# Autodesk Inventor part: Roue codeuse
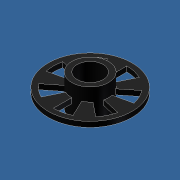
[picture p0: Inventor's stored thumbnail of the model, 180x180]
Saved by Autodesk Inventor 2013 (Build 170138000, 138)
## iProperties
Created: 2011-10
Part Number: Roue codeuse
Material: ABS (plastique)
Document SubType Name: Modeling
Designer: Laur
Mass: 0.0367757 g
Surface Area: 1.54299 cm^2
Volume: 0.034694 cm^3
Density: 1.06 g/cm^3
Author: Laur
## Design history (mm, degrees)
sketch "Esquisse3"
  geometry: L1 (1.24, -0.2)-(-1.24, -0.2) reference; L2 (1.24, -3.9)-(-1.24, -3.9) reference; L3 (0, -0.2)-(0, -3.9); L4 (-1.24, -0.2)-(-1.75, -0.2); L5 (-1.75, -1.45)-(-4, -1.45); L6 (-4, -1.45)-(-4, -1.95); L7 (-4, -1.95)-(-1.75, -1.95); L8 (-1.75, -1.95)-(-1.75, -3.2); L9 (-1.75, -3.2)-(-1.24, -3.2); L10 (-1.75, -1.45)-(-1.75, -0.2); L11 (-1.24, -0.2)-(-1.24, -3.2); L12 (-1.24, -0.2)-(-1.24, -3.2)
  constraints: 20 end point, 4 perpendicular, 3 parallel, 2 midpoint, 2 point on line, 1 collinear
  dimensions: "d0" = 3.5 diameter of L8 L3; "d1" = 3.5 diameter of L10 L3 (= d0); "d2" = 3 distance between parallel lines of L9 L4; "d3" = 0.5 distance between parallel lines of L7 L5; "d4" = 8 diameter of L6 L3; "d5" = 1.25 distance between parallel lines of L4 L5 (= 0.5 x d2 - 0.5 x d3); "d18" = 2.48 diameter of L11 L3 (derived)
revolve "forme générale" sketch "Esquisse3" stored, may be unused: angle "d6" = 90 deg
sketch "Esquisse4"
  geometry: L1 (0.767, 1.573)-(1.534, 3.146); L2 (0, 1.75)-(0, 3.5); L3 (0, 0)-(0.767, 1.573); L4 (0, 1.75)-(0, 0); C1 r 4 at (0, 0) reference; C2 r 4 at (0, 0) reference; A1 r 1.75 centre (0, 0) between (0, 1.75) and (0.767, 1.573) reference; A2 r 3.5 centre (0, 0) between (0, 3.5) and (1.534, 3.146)
  constraints: 8 end point, 4 point on circle, 2 collinear, 1 centre point, 1 coincident, 1 vertical
  dimensions: "d7" = 0.5 radial gap between concentric circles of A2 C2; "d8" = 26 deg angle of L1 L2
extrude "ouverture 26°" cut sketch "Esquisse4" stored distance "d13" = 10; taper "d14" = 0 deg
pattern_circular "Réseau 7 ouvertures" dims angle "d16" = 360 deg
node "Solide1"
node "Corps solides"
node "Corps surfaciques"
node "Référence2"
node "Référence3"
